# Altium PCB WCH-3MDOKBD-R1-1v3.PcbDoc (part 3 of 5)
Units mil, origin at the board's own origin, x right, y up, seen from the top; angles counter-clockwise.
Board outline 11710.74 x 4477.49 mil, 2 copper layers (Top Layer, Bottom Layer); 422 components, 246 nets, 927 pads, 1295 vias.
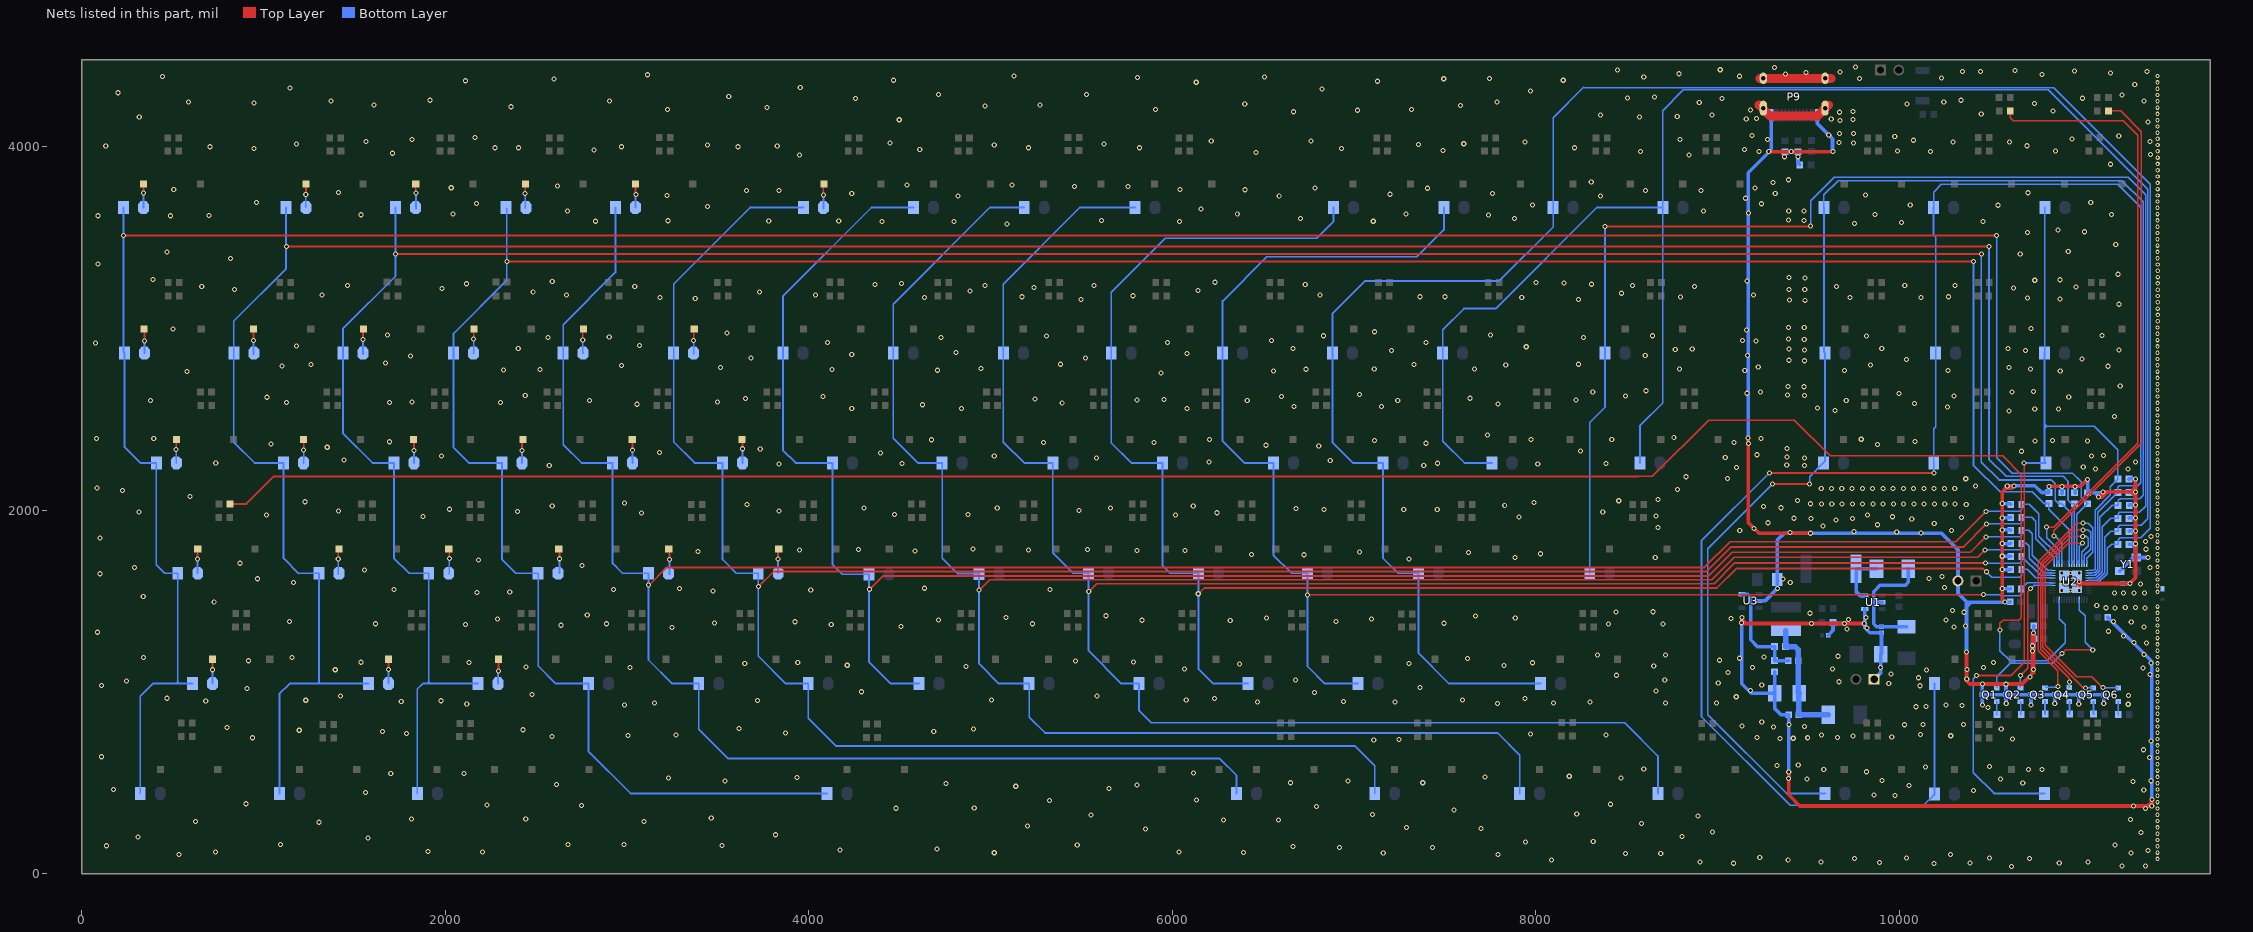
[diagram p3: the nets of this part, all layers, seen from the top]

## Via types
v1: diameter 28, hole 16, Top Layer to Bottom Layer, tented both sides, 1167 vias
v2: diameter 24, hole 12, Top Layer to Bottom Layer, tented both sides, 128 vias

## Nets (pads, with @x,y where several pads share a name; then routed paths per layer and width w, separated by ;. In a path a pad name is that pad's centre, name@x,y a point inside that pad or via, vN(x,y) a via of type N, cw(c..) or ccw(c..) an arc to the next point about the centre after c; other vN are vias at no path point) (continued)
BT-: C2.1 C3.1 C5.1 C6.1 C7.1 C8.1 C9.1 C11.2 C12.2 C13.2 C14.1 E1.0 J1.1 P7.2 P9.0 P9.A1 P9.B1 Q1.3 Q2.3 Q3.3 Q4.3 Q5.3 Q6.3 R10.2@9370.04,3970.81 R11.2@9442.13,3971.71 R128.1 R129.1 R133.1 RJ1.1 RJ2.1 RJ3.1 RJ4.1 RJ5.1 RJ6.1 RJ7.1 RJ8.1 RJ9.1 RJ10.1 RJ11.1 RJ12.1 RJ13.1 RJ14.1 RJ15.1 RJ16.1 RJ17.1 U1.4 U2.0 U3.2 Y1.2 Y1.4 | length 18642.1
  Top Layer w20: v1(9134.61,1409.74) 9134.61,1395.68 ; v1@9168.65,2396.61 v1(9168.65,2366) 9168.65,1931.1 9227.54,1872.21 v1(9511.69,1872.21) ; v1(9281,3971.58) v1(9404.61,3971.58) v1@9636.45,3971.58 ; v1@9390.47,558.96 v1(9390.47,523.09) 9390.47,433.13 9452.07,371.53 11365.06,371.53 ; v1(9806.35,1376.09) v1(9697.77,1376.09) 9154.21,1376.09 ; v1(10368.6,1218.87) 10368.6,1061.6 10387.56,1042.64 10674.23,1042.64 10731.29,1099.71 ; v1(10579.88,1493.79) 10565.71,1507.95 v1(10565.71,1567.63) v1(10565.71,1671.91) v1(10565.71,1745.7) v1(10565.71,1814.83) v1(10565.71,1890.97) v1(10565.71,1956.97) v1(10565.71,2035.15) 10565.71,2100.44 v1@10586.22,2120.95 ; v1(10593.28,2131.64) v1@10628.4,2131.64 ; v1@10595.1,2129.83 v1@10586.22,2120.95 ; v1(10629.12,2132.36) v1@10628.4,2131.64 ; v1(10731.29,1253.25) v1@10731.29,1224.34 ; v1(10732.16,1224.34) v1@10732.16,1225.2 ; v1(10822.87,2129.88) 10994.92,2129.88 v1(11034.05,2169.01) ; 10978.98,1596.12 11003.83,1596.12 ; v2@10988.26,1611.7 11003.83,1596.12 ; 10991.91,1584.2 11003.83,1596.12 ; v1@11120.34,2100.12 v1@11125.31,2100.12 ; v1(11298.76,2171.58) 11298.76,2124.66 ; v1(11389.33,408.45) v1@11389.33,395.8 ; 9134.61,1395.68 9154.21,1376.09 ; 9134.61,1395.68 9134.61,1379.16 9131.54,1376.09 9154.21,1376.09 ; v1@10586.22,2120.95 10617.7,2120.95 v1@10628.4,2131.64 ; 10731.29,1099.71 v1@10731.29,1224.34 ; 10731.29,1099.71 10738.13,1106.55 v1@10738.13,1231.18 ; v1@10731.29,1224.34 v1@10732.16,1225.2 ; v1@10732.16,1225.2 10732.16,1317.23 v1(10738.13,1323.21) v1@10738.13,1231.18 ; v1@10732.16,1225.2 v1@10738.13,1231.18 ; 11003.83,1596.12 v1(11267.28,1596.12) 11298.76,1627.61 v1(11298.76,1814.3) v1(11298.76,1885.75) v1(11298.76,1957.21) v1(11298.76,2028.66) 11298.76,2075.34 ; v1@11125.31,2100.12 v1(11095.82,2070.63) 11116.06,2070.63 11145.55,2100.12 ; v1@11125.31,2100.12 11145.55,2100.12 ; 11145.55,2100.12 11273.98,2100.12 ; 11273.98,2100.12 11298.76,2075.34 ; 11273.98,2100.12 11274.22,2100.12 ; 11274.22,2100.12 11298.76,2124.66 ; 11274.22,2100.12 v1(11298.76,2100.12) ; 11298.76,2075.34 v1(11298.76,2100.12) ; v1(11298.76,2100.12) 11298.76,2124.66 ; 11365.06,371.53 v1(11387.76,371.53) 11389.33,373.1 v1@11389.33,395.8 ; 11365.06,371.53 v1@11389.33,395.8
  Top Layer w50: 9228.25,4229.01 9289.92,4167.33 9547.79,4167.33 P9.0@9608.53,4228.08 ; P9.0@9233.05,4374.91 P9.0@9251.14,4374.91 P9.0@9591.3,4374.91 9622.76,4374.91
  Bottom Layer w20: v1(9131.93,1379.85) 9131.93,1407.06 v1(9134.61,1409.74) ; v1@9131.93,1380.56 9131.93,1045.07 9185.17,991.82 C12.2@9313.23,991.82 ; v1@9168.14,2363.04 9168.14,3855.24 9294.26,3981.36 P9.A1@9294.26,4172.15 ; U3.2@9228.25,1500.05 9260.48,1500.05 v1(9328.59,1568.15) C13.2@9328.59,1617.07 ; C12.2@9310.83,989.42 C12.2@9313.23,991.82 ; R133.1@9313.87,1111.26 9313.87,992.47 C12.2@9313.23,991.82 ; C13.2@9331.11,1614.55 C13.2@9328.59,1617.07 ; v1(9368.29,3943.47) 9370.04,3945.23 R10.2@9370.04,3970.81 9370.94,3971.71 R11.2@9442.13,3971.71 v1@9442.13,3943.81 ; v1@9390.37,523.09 v1@9390.42,523.14 ; v1(9390.47,523.09) v1@9390.42,523.14 ; v1(9391.29,558.96) 9391.29,524.01 v1@9390.42,523.14 ; v1(9442.47,3943.47) v1@9442.13,3943.81 ; R128.1@9452.55,3898.85 9442.13,3909.27 v1@9442.13,3943.81 ; P9.B1@9548.19,4172.15 9548.19,4125.84 9631.52,4042.51 v1@9631.52,3971.58 ; C5.1@9607.68,1311.74 9634.85,1338.91 R129.1@9634.85,1380.06 9635.78,1381 9640.69,1376.09 v1(9697.77,1376.09) ; U1.4@9809.52,1455.37 9809.52,1352.67 9837.07,1325.11 C3.1@9901.41,1325.11 9901.41,1209.4 C2.1@9898.17,1206.15 9898.17,1106.53 J1.1@9860.69,1069.05 ; v1(10368.6,1218.87) 10368.6,1469.66 ; v1(10456.21,928.26) Q1.3@10456.21,984.15 ; v1@10456.21,1044.2 Q1.3@10456.21,984.15 ; v1(10565.71,1567.63) 10567.31,1566.03 RJ11.1@10610.94,1566.03 ; v1(10565.71,1671.91) 10610.27,1671.91 RJ10.1@10611.9,1673.55 ; v1(10565.71,1745.7) 10611.31,1745.7 RJ9.1@10611.9,1745.11 ; v1(10565.71,1814.83) 10610.08,1814.83 RJ8.1@10611.9,1816.66 ; v1(10565.71,1890.97) 10609.15,1890.97 RJ7.1@10611.9,1888.22 ; v1(10565.71,1956.97) 10609.11,1956.97 RJ6.1@10611.9,1959.77 ; v1(10565.71,2035.15) 10608.07,2035.15 RJ5.1@10611.9,2031.32 ; v1@10586.15,1042.93 10585.92,1042.7 Q2.3@10585.92,984.15 ; v1(10587.65,935.73) 10585.92,937.46 Q2.3@10585.92,984.15 ; v1(10593.28,2131.64) 10595.95,2134.31 10744.21,2134.31 10782.35,2096.17 RJ4.1@10822.08,2096.17 v1@10822.08,2129.88 ; C6.1@10610.12,1495.6 10606.4,1491.87 10390.81,1491.87 ; v1(10723.81,926.49) 10723.81,982.13 Q3.3@10721.79,984.15 ; C9.1@10739.29,1363.92 10739.29,1294.13 C8.1@10741.11,1292.32 C8.1@10741.11,1281.6 ; v1(10854.28,936.5) 10855.32,937.54 Q4.3@10855.32,984.15 ; Q4.3@10855.32,985.04 Q4.3@10855.32,984.15 ; RJ3.1@10894.47,2090.85 v1@10894.47,2129.89 ; RJ2.1@10966.38,2094.01 v1(10966.38,2128.9) ; v1(10986.51,933.46) 10987.29,934.24 Q5.3@10987.29,984.06 ; v1@11034.95,2172.09 RJ1.1@11034.95,2095.15 11075.48,2095.15 ; v1(11123.7,934.83) Q6.3@11123.7,983.69 11123.25,984.15 Q4.3@10855.32,984.15 ; C14.1@11145.05,1410.61 11387.76,1167.9 v1(11387.76,371.53) ; Y1.4@11211.35,1663.76 11286.16,1738.56 Y1.2@11301.9,1738.56 ; C7.1@11228.28,1596.06 11267.21,1596.06 v1(11267.28,1596.12) ; RJ16.1@11262.57,2097.64 11265.05,2100.12 v1(11298.76,2100.12) ; RJ17.1@11262.9,2169.74 11264.73,2171.58 v1(11298.76,2171.58) ; RJ12.1@11263.19,1811.41 RJ12.1@11278.15,1811.41 ; RJ13.1@11263.19,1882.98 11265.96,1885.75 v1(11298.76,1885.75) ; RJ14.1@11263.19,1954.56 11265.84,1957.21 v1(11298.76,1957.21) ; RJ15.1@11263.22,2026.18 11265.7,2028.66 v1(11298.76,2028.66) ; v1(11366.65,1738.56) Y1.2@11301.9,1738.56 ; C12.2@9313.23,991.82 9313.23,909.25 9347.79,874.69 C11.2@9390.37,874.69 9390.37,523.19 v1@9390.42,523.14 ; C13.2@9328.59,1617.07 C13.2@9328.59,1618.92 ; C13.2@9328.59,1617.07 C13.2@9327.66,1618 C13.2@9328.59,1618.92 ; C13.2@9328.59,1618.92 9328.59,1834.58 9367.15,1873.15 10229.88,1873.15 10321.86,1781.17 P7.2@10321.86,1610.46 10321.86,1542.72 10372.71,1491.87 ; 10368.6,1469.66 10368.6,1487.76 10372.71,1491.87 ; 10368.6,1469.66 10390.81,1491.87 ; 10372.71,1491.87 10390.81,1491.87 ; Q1.3@10456.21,984.15 Q2.3@10585.92,984.15 ; Q2.3@10585.92,984.15 Q3.3@10721.79,984.15 ; Q3.3@10721.79,984.15 Q4.3@10855.32,984.15 ; v1@10732.16,1254.11 v1(10732.16,1224.34) 10741.11,1233.29 v1@10741.11,1263.06 ; v1@10732.16,1254.11 v1@10741.11,1263.06 ; v1@10732.16,1254.11 v1(10731.29,1253.25) 10731.29,1271.79 C8.1@10741.11,1281.6 ; v1@10741.11,1263.06 C8.1@10741.11,1281.6 ; 11075.48,2095.15 11096.31,2095.15 ; 11075.48,2095.15 11095.82,2074.81 v1(11095.82,2070.63) v1@11101.3,2076.11 ; 11096.31,2095.15 11120.34,2095.15 v1@11101.3,2076.11 ; 11096.31,2095.15 11101.3,2090.17 v1@11101.3,2076.11 ; RJ12.1@11278.15,1811.41 11298.76,1790.79 ; RJ12.1@11278.15,1811.41 11295.87,1811.41 v1(11298.76,1814.3) 11298.76,1790.79 ; 11298.76,1790.79 11298.76,1741.7 Y1.2@11301.9,1738.56
  other v1: 10616.69,38.55 11353.1,41.42 11224.51,42.39 10190.38,55.82 9086.16,56.93 10879.06,57.29 10387.53,58.23 9889.91,61.17 8903.75,63.22 11036.8,63.54 9568.59,64.45 8086.02,75.8 9388.09,75.8 9752.21,82.28 10715.08,83.84 10039.73,85.55 10494.88,86.96 9231.81,87.96 535.01,104.42 10280.92,104.14 7792.09,105.61 8493.74,110.26 8686.74,110.4 11273.82,112.97 5020.42,114.86 7160.4,114.45 6390.92,115.13 737.76,118.41 2205.95,118.41 6037.59,118.17 1905.1,121.77 11366.64,126.51 4172.96,130.96 4706.54,136.45 6920.63,142.54 7430.58,143.5 6665.04,148.63 136.5,153.36 3522.04,155.25 11185.84,156.49 5477.15,157.77 1094.31,160.35 2676.82,160.11 2982.85,160.11 7943.19,174.35 8315.79,176.73 1576.73,195.31 311.28,202.3 8803.5,203.91 3818.36,213.54 11328.94,227.07 8972.36,229.76 5852.5,246.23 7698.76,247.92 7288.88,252.82 5203.02,261.33 8582.03,275.46 1305.86,282.43 625.89,286.2 3094.58,286.4 6583.62,294.38 6280.78,295.65 11270.93,298.62 1814.44,300.18 2443.66,300.98 3463.75,305.83 8892.29,316.81 5553.89,321.88 7100.41,324.88 8224.94,328.47 7549.25,349.97 11353.41,358.72 4479.13,359.48 4910.61,361.84 6792.86,368.44 11287.35,371.04 2749.69,373.84 2230.78,377.97 8410.47,381.74 905.55,384.08 5324.85,401.44 6132.53,404.36 9974.66,430.5 9860.11,432.9 1562.74,447 10406.53,456.16 11343.91,460.69 176.56,462.83 5650.76,468.45 5139.06,480.63 10053.68,485.21 5806.38,486.73 2613.67,490.42 4755.88,495.28 6649.77,499.9 7377.84,499.9 10678.41,499.53 11284.94,505.6 3539.61,509.19 6966.03,509.79 11384.5,511.03 9904,512.56 10555.61,520 9491.58,520.73 3227.75,526.05 8468.31,526.26 3934.94,529.28 7719.46,530.66 8183.47,535.31 1701.01,551.66 2104.85,551.66 6116.06,552.62 9817.67,560.21 10710.81,572.02 9583.81,572.61 10785,572.87 8593.5,575.68 10142.28,586.6 10495.07,588.22 9327.39,595.55 9443.11,597.36 11376.05,637.75 108.53,642.76 11342.86,681.19 11383.89,730.07 7108.3,734.59 7247.74,737.43 10621.83,741.08 9341.84,743.45 9416.01,744.43 940.04,747.56 9495.36,747.57 9659.7,747.81 9216.59,748.17 9957.65,752.26 2586.9,755.26 9745.25,756.94 10282.48,758.5 3007,760.38 3269.89,762.05 9571.29,762.05 8385.11,763.06 10115.38,764.75 7970.76,768.61 1787.68,770.63 3873.21,773.34 1654.47,780.88 4687.87,781.88 1197.35,788.68 2428.07,791.12 10560.11,795.79 4906.46,796.45 3616.28,797.32 800.29,804.2 9308.3,805.82 9477.15,809.68 9133.78,811.58 10028.23,818.69 9392.99,819.55 10128.51,819.55 10352.76,820.97 9242.79,834.64 10486.92,912.87 10090.56,917.97 10146.49,918.79 10344.71,924.55 2987.53,926.41 10255.06,927.84 11258.52,931.62 2118.99,932.41 7788.82,934.78 8097.61,938.57 3151.89,939.06 8713.59,939.19 8994.3,939.06 7225.45,942.87 6468.27,944.71 8296.84,944.66 1758.39,947.2 6942.44,947.67 682.93,949.14 1976.89,950.96 3717.4,951.86 1233.08,953.42 5005.03,955.79 6076.55,955.28 7596.33,955.28 470.61,964.58 6232.11,964.26 7940.38,964.26 9102.54,972.65 1424.01,976.98 5586.8,977.11 11260.53,980.01 2477.6,985.41 6782.59,997.17 4289.55,1000.47 8660.96,1005.55 9179.89,1008.38 909.85,1019.13 7362.98,1024.09 10113.08,1033.27 108.53,1034.28 9242.36,1038.05 10586.19,1041.62 10456.15,1042.69 9941.08,1046.14 9003.34,1049.26 9668.23,1055.32 248.01,1059.79 6677.88,1065.98 8709.01,1065.04 10370.12,1069.9 10105.07,1077.29 10717.71,1082.27 8442.72,1091.37 11378.35,1096 9953.76,1098.55 9056.37,1107.21 10149.09,1119.3 1395.37,1121.39 10370.6,1121.91 10737.76,1122.39 6067.57,1125.81 9631.8,1125.29 11339.29,1131.18 3017.03,1132.92 10463.35,1133.21 9192.39,1134.88 9896.29,1134.05 2443.88,1137.13 4864.93,1138.54 8648.53,1142.74 7823.7,1143.76 4211.82,1146.2 6369.73,1152.74 3648.34,1155.91 7303.15,1155.73 11382.83,1158.72 7982.35,1160.01 3939.8,1160.77 10518.17,1161.69 1537.8,1162.42 2131.55,1162.08 5785.74,1164.76 5468.01,1169 918.28,1170.85 9009.94,1173.57 7623.26,1182.65 9120.55,1184.85 1157.32,1188.52 340.66,1189.76 9254.86,1191.1 9662.72,1195.67 8339.23,1202 8713.59,1201.57 11345.51,1205.81 11358.65,1268.24 11289.54,1271.56 11232.74,1305.99 87.56,1327.92 11150.37,1333.18 9711.82,1346.48 9821.78,1350.39 3246.97,1353.28 10299.66,1356.64 11345.3,1357.36 4508.1,1359.8 10363.7,1361.33 2636.84,1366.08 2112.04,1370.35 4123.86,1370.05 8398.82,1372.89 8698.34,1373.95 1617.1,1374.62 2888.57,1374.62 5231.92,1374.51 9515.86,1376.4 7494.61,1377.11 3481.64,1378.88 11275.04,1383.8 3924.05,1385.42 6900.45,1385.93 1143.49,1387.42 11178.33,1387.58 6318.88,1392.07 5834.26,1393.94 4713.03,1395.66 10256.76,1395.3 9720.27,1398.81 2286.97,1400.22 7096.72,1401.05 9073.62,1402.75 6519.32,1407.03 7886.53,1407.03 5086.19,1408.51 9815.53,1408.18 7668.13,1416.01 5635.1,1418.22 2781.9,1421.55 9507.36,1432.14 10355.89,1437.85 8441.8,1438.79 8644.94,1440.3 10292.8,1447.56 11186.79,1461.24 11349.89,1461.71 11135.56,1462.65 11242.26,1463.59 11298.19,1464.06 11085.27,1475.81 729.62,1494.08 339.25,1523.68 11182.77,1543.07 11232,1543.07 11289.42,1543.07 11348,1543.96 2176.04,1545.28 2355.24,1549.55 3473.11,1553.82 4011.15,1559.6 1719.5,1562.35 2926.97,1562.35 5328.27,1562.7 3290.08,1568.41 4636.18,1569.85 10247.97,1574.19 11326.87,1593.48 1164.83,1600.75 9399.25,1600.5 9359.88,1620.18 968.56,1622.08 10162.22,1623.47 10233.97,1633.82 101.54,1649.52 1557.36,1669.02 290.3,1684.48 11378.35,1684.48 2752.04,1694.62 870.43,1707.42 2184.57,1724.48 7302.6,1731.42 7884.77,1738.16 8656.76,1739.72 6724.94,1753.89 6434.99,1756.14 8025.28,1759.74 7628.53,1767.38 7030.63,1769.63 3392.04,1771.42 4584.39,1774.51 5805.14,1777.49 6070.13,1777.49 3950.19,1780.47 5209.65,1780.47 4274.73,1783.44 5534.19,1783.44 11355.46,1784.47 4902.97,1786.42 11353.07,1826.66 101.54,1845.28 11382.83,1854.93 10119.52,1874.37 9397.3,1875.76 9984.97,1879.87 9750.63,1882.93 9121.76,1887.12 10285.76,1888.31 9199.25,1898.38 8672.24,1904.23 9580.16,1911.41 9879.55,1918.86 10191.4,1925.87 9276.63,1929.82 9650.4,1945.16 10067.66,1950.07 9512.5,1952.98 9742.49,1952.36 9419.7,1954.91 10342.33,1959.59 7906.12,1962.3 9962.15,1962.98 1877.35,1963.42 8660.35,1967.11 1018.21,1971.9 6018.59,1973.73 9824.31,1973.57 4472.24,1974.58 4876.97,1974.58 3080.56,1984.75 6244.87,1984.83 315.82,1988.98 8367.88,1989.44 2397.68,1991.03 1414.4,1993.66 3836.96,1995.08 5486.15,1997.22 6835.08,2003.39 7273.39,2003.39 7457.71,2003.39 2024.84,2004.21 6679.98,2007.88 4305.16,2010.11 5660.82,2010.45 5037.01,2012.02 9348.05,2012.66 9252.55,2019.13 2589.39,2022.22 6115.2,2023.05 7828.58,2025.87 10367.37,2029.38 3660.44,2030.19 9571.29,2032.46 9627.77,2032.46 9684.25,2032.46 9740.74,2032.46 9797.22,2032.46 9853.7,2032.46 9910.18,2032.46 9966.67,2032.46 10023.15,2032.46 10079.63,2032.46 10136.12,2032.46 10192.6,2032.46 10249.08,2032.46 10305.56,2032.46 9511.18,2034.42 2987.08,2038.11 7988.71,2042.04 1229.71,2045.33 8455.72,2051.28 9439.91,2053.17 8671.4,2058.04 597.36,2074.35 11120.14,2099.7 226.15,2108.49 8780.04,2112.28 9569.74,2118.47 9626.22,2118.47 9682.71,2118.47 9739.19,2118.47 9795.67,2118.47 9852.16,2118.47 9908.64,2118.47 9965.13,2118.47 10021.61,2118.47 10078.09,2118.47 10134.58,2118.47 10191.06,2118.47 10247.54,2118.47 10304.03,2118.47 85.35,2121.29 10893.83,2129.62 10419.28,2131.58 9055.05,2172.46 10364.97,2172.31 8826.48,2183.08 11256.74,2224.76 11079.57,2226.43 9104.79,2234.04 11011.16,2236.97 2572.82,2245.02 7383.06,2244.65 9477.15,2244.65 9380.01,2248.1 8010.54,2253.72 3835.66,2254.16 8386.35,2255.92 4513,2256.9 738.16,2257.82 7459.95,2257.38 6201.6,2264.06 11298.19,2264.06 6868.71,2273.48 1444.59,2275.42 9477.38,2285.35 5583.97,2287.1 9042.02,2288.52 9381.19,2291.74 1979.75,2296.22 5020.42,2297.35 11055.47,2298.33 11123.09,2298.97 9217.3,2303.91 4395.39,2312.72 3178.7,2317.55 10671.72,2323.46 8244.57,2324.42 3733.37,2334.62 9382.23,2339.05 1351.26,2345.42 6805.86,2351.78 6515.9,2356.28 9878.63,2359.54 1041.17,2362.51 7394.77,2367.52 5290.86,2371.35 5898.78,2371.86 9089.12,2372.34 1694.56,2375.42 10086,2377.03 10745.79,2379.4 11034.6,2380.22 10842.12,2383.01 7111.57,2383.44 4676.46,2386.42 7972.44,2387.75 8417.32,2387.76 6205.65,2388.96 9789.86,2389.52 81.09,2394.35 397.27,2394.17 9238.27,2394.35 9166.98,2396.61 8758.74,2398.69 7733.48,2412.24 11182.58,2513.7 10602.24,2544.17 9644.68,2547.81 10744.42,2554.94 10874.4,2556.02 4236.57,2558.63 4841.1,2558.63 6080.93,2558.63 9549.07,2561.53 10264.52,2567.04 6668.75,2569.81 7149.76,2569.81 4625.93,2579.12 3054.97,2582.09 7792.07,2584.25 10082.67,2585.47 5394.42,2589.37 1126.43,2590.62 1693.9,2590.62 2304.04,2590.62 1817.63,2594.89 3498.83,2594.49 9707.45,2602.06 379.76,2603.42 2794.7,2603.42 6412.51,2603.53 7240.44,2603.08 5806.38,2605.78 8219.69,2605.78 5955.36,2607.47 5245.84,2609.86 3652.96,2613.97 7638.38,2614.99 1019.76,2620.49 10931.59,2621.06 6601.32,2623.76 4077.74,2625.23 2440.57,2629.02 8493.91,2628.26 10300.86,2628.37 9477,2630.17 9384.52,2632.08 7030.63,2635 9997.02,2639.98 9162.32,2642.25 10618.45,2648.27 9235.98,2649.47 8312.72,2650.18 10736.68,2652.17 8604.99,2656.26 9387.07,2678.48 9475.09,2678.16 11214.58,2682.91 5937.48,2753.31 580.29,2761.29 10884.8,2763.9 6556.36,2765.36 9149,2767.76 9696.97,2767.2 4707.9,2768.68 10266.97,2768.08 2321.1,2769.82 4128.98,2773.8 2521.64,2774.09 6736.18,2774.35 7110.86,2775.71 7662.71,2775.16 8790.61,2776.61 10720.55,2776.21 4948.69,2778.93 10603.68,2783.56 3514.19,2784.05 9223.22,2787.11 11146.31,2790.81 1102.1,2791.99 2969.64,2795.42 7834.46,2798.39 9840.67,2798.82 1262.96,2799.69 5385.07,2801.69 7329.58,2801.33 8235.32,2802.13 1672.57,2808.22 9478.3,2821.15 9393.37,2824 10037.9,2828.81 11004.12,2829.98 3683.26,2835.28 5522.49,2835.28 1809.1,2846.62 8601.8,2850.78 9164.8,2850.61 4236.57,2855.78 6080.93,2860.9 4810.36,2866.02 7205.95,2878.33 10692.43,2878.16 11207.24,2879.31 9478.3,2880.39 8766.78,2882.44 9393.37,2885.39 8860.29,2886.74 6664.28,2887.88 9902.82,2887.88 2402.17,2889.29 10596.43,2889.47 7947.27,2898.23 1181.89,2902.09 3068.93,2904.27 76.82,2919.16 7394.76,2920.46 4103.36,2922.38 5973.33,2922.38 9211.38,2930.41 6545.12,2931.7 9137.62,2932.19 9476.16,2938.92 9390.47,2941.01 2566.4,2947.99 4728.39,2947.99 8262.4,2949.68 2902.93,2951.59 9818.42,2956.81 5307.32,2958.24 6832.84,2958.67 8642.26,2958.67 11114.38,2959.11 1682.73,2962.97 7749.88,2963.57 3550.06,2973.61 7112.52,2980.87 9159.3,2989.83 502.72,2996.14 10722.65,2998.28 9389.8,3003.15 9476.59,3003.96 11207.24,3131.76 9481.32,3153.74 9394.44,3155.02 5496.88,3158.05 8235.42,3158.72 10883.7,3160.78 3375.87,3163.17 10705.25,3166.58 3181.19,3168.29 4636.18,3168.29 7922.59,3169.24 9727.95,3169.79 10119.41,3169.79 8794.83,3172.77 5174.12,3173.42 7361.72,3173.42 7500.05,3173.42 10269.06,3173.49 5783.78,3178.54 1322.69,3183.69 2668.54,3183.33 4036.76,3183.66 6813.54,3183.66 9197.87,3183.69 8471.43,3192.43 3729.37,3199.03 2484.42,3199.15 4887.22,3204.15 6140.45,3208.19 9479.18,3212.27 840.55,3213.56 9392.3,3213.55 1981.69,3218.71 10628.35,3220.26 5238.32,3224.82 10970.75,3227.52 3042.86,3229.77 9654.16,3229.22 661.35,3230.62 8871.52,3230.64 1463.49,3234.89 4969.19,3234.89 5568.61,3234.89 10305.4,3234.82 8532.12,3235.14 10029.23,3235.37 4364.64,3240.02 6731.57,3240.02 8305.1,3241.88 2117.62,3244.6 4511.05,3245.62 8154.53,3248.6 8001.69,3250.98 6236.01,3253.24 2589.42,3258.13 9160.93,3259.66 10744.42,3263.79 10883.7,3266.69 392.55,3269.02 9479.61,3277.32 9392.72,3278.59 11202.9,3297.16 89.61,3354.36 819.22,3384.22 10664.63,3408.88 469.35,3418.36 10928.68,3421.94 11189.84,3459.66 10705.25,3526.4 11017.19,3530.75 10872.1,3539.46 5091.79,3573.13 9753.85,3575.76 10010.57,3582.3 10458.95,3586.47 4403.62,3587.22 4798.47,3587.22 6039.51,3587.95 2827.68,3588.39 7105.57,3588.39 3780.32,3590.04 4165.44,3590.73 3225.74,3591.22 5610.73,3592.87 9473.9,3593.42 9389.58,3596.47 6705.96,3603.76 7883.57,3603.78 89.61,3618.89 489.2,3618.8 701.55,3619.13 7740.5,3623.59 1536.64,3624.26 9865.04,3626.45 11166.62,3626.51 7284.96,3628.45 2043.83,3629.38 6357.58,3629.38 9170.68,3633.53 2673.99,3644.75 8922.61,3644.1 9391.29,3644.75 9474.28,3644.16 6157.77,3655 3442.47,3670.36 10542.35,3676.46 7981.25,3677.88 10059.63,3677.14 9240.5,3684.86 2171.91,3685.73 962.84,3690.86 11052.36,3691.23 9154.12,3714.85 4820.61,3726.72 6588.12,3726.72 8355.63,3726.72 3220.8,3729.46 9814.35,3732.73 7197.78,3736.97 9316.89,3740.75 4236.57,3742.09 7761.33,3742.09 10706.7,3745.47 1413.68,3747.21 3657.64,3757.46 3836.96,3757.46 8604.17,3758.5 8908.7,3758.5 506.87,3762.58 6400.43,3762.09 6042.36,3763.4 7403.34,3770.2 9206.33,3770.83 2033.58,3772.83 6784.21,3772.23 5461.26,3779.01 5757.4,3779.01 2617.63,3783.07 5117.17,3787.47 4541.45,3788.11 9304.62,3801.03 8304.59,3804.28 9389.59,3817.08 11161.63,3902.08 3949.67,3952.14 8841.92,3952.9 11381.03,3955.98 1710.83,3962.39 6460.04,3967.51 8575.93,3972.64 9634.7,3972.2 9226.94,3973.1 10169.88,3973.26 10857.89,3974 9989.13,3974.85 7489.81,3977.76 2819.2,3980.34 4610.56,3982.88 9146.92,3983.58 947.47,3988 6931.38,3988.01 2273.61,3992.85 2402.45,3993.13 5209.97,3993.13 5819.64,3993.13 8212.18,3993.13 706.68,3998.25 2971.13,3998.25 3611.54,3998.25 132.88,4003.37 3826.71,4003.37 10702.34,4003.73 3442.47,4008.5 5020.41,4008.5 7354.67,4010.18 1183.13,4013.62 5624.83,4013.1 7603.1,4015.05 4446.61,4018.74 9748.34,4018.67 9668.07,4020.94 7940.65,4023.87 10294.65,4024.04 10606.45,4024.67 1563.99,4027.34 11377.48,4027.47 6762.31,4028.99 6214.29,4030.02 10077.03,4034.19 8793.49,4038.02 9273.94,4037.55 1818.41,4039.23 10949.06,4041.72 2164.47,4049.14 9974.13,4055.8 11206.6,4057.58 9188.87,4060.84 9610.93,4063.05 9748.34,4070.92 9670.34,4072.05 11366.49,4134.23 9672.39,4143.36 4497.85,4146.82 9743.86,4148.26 9624.64,4150.4 9157.31,4151.53 9214.43,4153.55 317.31,4162.19 8570.8,4162.19 8777.87,4164.42 8355.63,4172.44 8969.57,4172.45 10449.91,4179.62 9671.09,4188.29 6667.14,4191.01 9744.92,4192.08 10843.95,4195.31 7019.14,4199.2 9180.09,4201.33 3222.17,4203.18 5906.74,4203.18 7315.62,4203.18 3770.35,4213.42 2361.47,4218.55 4969.18,4223.67 7586.05,4224.51 1608.36,4228.79 5271.45,4228.79 6398.56,4233.92 10042.48,4233.7 10742.82,4235.42 947.47,4239.04 8898.61,4242.36 588.84,4244.16 7786.95,4244.17 10243.91,4245.21 1372.69,4249.29 2904.53,4249.29 11346.26,4251.12 10338.9,4253.95 1915.75,4254.41 4257.06,4264.66 9024.88,4264.28 8503.07,4265.46 11006.09,4265.06 8651.73,4272.29 3560.3,4274.9 11224.89,4282.58 4713.02,4285.15 5527.61,4285.15 199.48,4295.39 7971.39,4305.64 6823.79,4315.89 1147.27,4321.01 3953.48,4324.88 11294.56,4341.02 6131.81,4353.28 7129.65,4358.83 2111.6,4361.44 4467.09,4364.23 8150.61,4364.44 2599.39,4370.55 7493.36,4372.66 9779.43,4372.95 7745.57,4374.83 10232.4,4376.22 5807.6,4379.3 6507.52,4382.57 8593.62,4383 446.09,4385.95 9120.88,4386.36 5128.77,4387.18 3112.28,4394.62 10784.44,4395.71 9374.31,4399.42 8786.27,4400.19 11161.21,4404.32 9486.06,4406.76 9673.87,4410.31 10347.4,4412.73 10446.27,4413.44 11362.1,4413.15 10962.99,4415.14 10634.68,4417.56 8449.96,4419.97 9014.44,4421.84 9313.27,4433.47 9758.82,4436.05
  other v2: 11419.5,80.86 11419.5,115.56 11419.5,150.26 11419.5,184.96 11419.5,219.66 11419.5,254.36 11419.5,289.07 11419.5,323.77 11419.5,358.47 11419.5,393.17 11419.5,427.87 11419.5,462.57 11419.5,497.28 11419.5,531.98 11419.5,566.68 11419.5,601.38 11419.5,636.08 11419.5,670.78 11419.5,705.49 11419.5,740.19 11419.5,774.89 11419.5,809.59 11419.5,844.29 11419.5,878.99 11419.5,913.7 11419.5,948.4 11419.5,983.1 11419.5,1017.8 11419.5,1052.5 11419.5,1087.2 11419.5,1121.91 11419.5,1156.61 11419.5,1191.31 11419.5,1226.01 11419.5,1260.71 11419.5,1295.42 11419.5,1330.12 11419.5,1364.82 11419.5,1399.52 11419.5,1434.22 11419.5,1468.92 11419.5,1549.49 10940.73,1557.7 11419.5,1583.53 10892.73,1605.7 10988.73,1605.7 11419.5,1618 11419.5,1652.7 10940.73,1653.7 11419.5,1687.4 11419.5,1722.1 11419.5,1756.8 11419.5,1791.51 11419.5,1826.21 11419.5,1860.91 11419.5,1895.61 11419.5,1930.31 11419.5,1965.01 11419.5,1999.72 11419.5,2034.42 11419.5,2069.12 11419.5,2103.82 11419.5,2138.52 11419.5,2173.22 11419.5,2207.93 11419.5,2242.63 11419.5,2277.33 11419.5,2312.03 11419.5,2346.73 11419.5,2381.43 11419.5,2416.14 11419.5,2450.84 11419.5,2485.54 11419.5,2520.24 11419.5,2554.94 11419.5,2589.65 11419.5,2624.35 11419.5,2659.05 11419.5,2691.99 11419.5,2726.7 11419.5,2761.4 11419.5,2796.1 11419.5,2830.8 11419.5,2865.5 11419.5,2900.2 11419.5,2934.91 11419.5,2969.61 11419.5,3004.31 11420.84,3038.56 11420.84,3073.27 11420.84,3107.97 11420.84,3142.67 11420.84,3177.37 11420.84,3212.07 11420.84,3246.77 11420.84,3281.48 11420.84,3316.18 11420.84,3350.88 11419.52,3385.13 11419.52,3419.84 11419.52,3454.54 11419.52,3489.24 11419.52,3523.94 11419.52,3558.64 11419.52,3593.35 11419.52,3628.05 11419.52,3662.75 11419.52,3697.45 11420.17,3730.4 11420.17,3765.1 11420.17,3799.81 11420.17,3834.51 11420.17,3869.21 11420.17,3903.91 11420.17,3938.61 11420.17,3973.31 11420.17,4008.02 11420.17,4042.72 11419.52,4075 11419.52,4109.71 11419.52,4144.41 11419.52,4179.11 11419.52,4213.81 11419.52,4248.51 11419.52,4283.21 11419.52,4317.92 11419.52,4352.62 11419.52,4387.32
CL0: D1.2 D7.2 D13.2 D19.2 D28.2 D34.2 RJ1.2 U2.20 | length 16248
  Top Layer w10: v1(231.49,3510.98) v1(10534.99,3510.98)
  Bottom Layer w7: U2.20@10975.43,1704.68 10975.43,1975.57 RJ1.2@11034.38,2034.52
  Bottom Layer w10: D1.2@230.22,3664.02 230.22,2869.68 D7.2@236.44,2863.47 236.44,2346.22 323.49,2259.16 D13.2@411.11,2259.16 411.11,1699.56 458.76,1651.91 D19.2@528.99,1651.91 528.99,1054.33 ; D34.2@322.75,440.87 322.75,976.26 391.71,1045.22 519.88,1045.22 ; D28.2@610.9,1045.22 538.09,1045.22 ; v1@10535.73,3510.98 10535.73,2288.04 10620.96,2202.81 10951.86,2202.81 10999.82,2154.86 10999.82,2069.66 RJ1.2@11034.95,2034.52 ; 519.88,1045.22 528.22,1045.22 ; 519.88,1045.22 528.99,1054.33 ; 528.22,1045.22 538.09,1045.22 ; 528.22,1045.22 528.99,1045.99 528.99,1054.33 ; 528.99,1054.33 538.09,1045.22
CL1: D2.2 D8.2 D14.2 D20.2 D29.2 D35.2 RJ2.2 U2.19 | length 15685.8
  Top Layer w10: v1(1127.92,3449.57) v1@10494.72,3449.57
  Bottom Layer w7: U2.19@10961.65,1704.68 RJ2.2@10961.65,2034.75
  Bottom Layer w10: D35.2@1088.31,440.87 1088.31,988.32 1145.22,1045.22 1295.04,1045.22 ; D2.2@1125.34,3664.02 1125.34,3327.9 837.44,3040 D8.2@837.44,2863.47 837.44,2373.14 951.43,2259.16 D14.2@1111.16,2259.16 1111.16,1733.71 1192.96,1651.91 D20.2@1306.18,1651.91 1306.18,1056.36 ; D29.2@1578.84,1045.22 1317.32,1045.22 ; v1(10491.96,3448.86) 10491.96,2279.86 10586.49,2185.33 10900.3,2185.33 10927.11,2158.52 10927.11,2054.43 10946.79,2034.75 10961.65,2034.75 RJ2.2@10963.33,2034.75 ; 1295.04,1045.22 1308.39,1045.22 ; 1295.04,1045.22 1306.18,1056.36 ; 1306.18,1056.36 1306.18,1047.43 1308.39,1045.22 ; 1306.18,1056.36 1317.32,1045.22 ; 1308.39,1045.22 1317.32,1045.22
CL2: D3.2 D9.2 D15.2 D21.2 D30.2 D36.2 RJ3.2 U2.18 | length 14826.9
  Top Layer w10: v1@1729.53,3409.04 10450.8,3409.04 v1@10453.09,3409.04
  Bottom Layer w7: RJ3.2@10895.63,2032.74 10947.87,1980.5 U2.18@10947.87,1704.68
  Bottom Layer w10: D3.2@1727.53,3664.02 v1(1727.53,3407.63) 1727.53,3287.33 1437.66,2997.46 D9.2@1437.66,2863.47 1437.66,2421.93 1600.44,2259.16 D15.2@1718.18,2259.16 1718.18,1735.34 1801.6,1651.91 D21.2@1909.59,1651.91 1909.59,1056.25 ; D36.2@1847.05,440.87 1847.05,1015.38 1876.89,1045.22 1898.57,1045.22 ; D30.2@2180.6,1045.22 1920.62,1045.22 ; v1@10450.03,3409.04 10450.03,3408.01 10450.03,2263.67 10547.94,2165.76 10835.42,2165.76 10856.93,2144.26 10856.93,2054.91 10876.48,2035.35 RJ3.2@10893.01,2035.35 ; 1898.57,1045.22 1910.11,1045.22 ; 1898.57,1045.22 1909.59,1056.25 ; 1909.59,1056.25 1909.59,1045.74 1910.11,1045.22 ; 1909.59,1056.25 1920.62,1045.22 ; 1910.11,1045.22 1920.62,1045.22
  other v1: 10450.8,3408.01
CL3: D4.2 D10.2 D16.2 D23.2 D31.2 D37.2 RJ4.2 U2.17 | length 15181.8
  Top Layer w10: v1(2339.34,3366.43) v1@10412.94,3366.43
  Bottom Layer w7: RJ4.2@10822.08,2035.54 10822.08,2003.39 10934.09,1891.38 U2.17@10934.09,1704.68
  Bottom Layer w10: D4.2@2339.34,3660.18 v1(2339.34,3366.43) 2339.34,3264.31 2046.27,2971.24 D10.2@2046.27,2863.47 2046.27,2343.49 2130.6,2259.16 D16.2@2312.37,2259.16 2312.37,1728.74 2389.19,1651.91 D23.2@2511.87,1651.91 2511.87,1142.13 2608.78,1045.22 D31.2@2788.24,1045.22 2788.24,672.31 3019.69,440.87 D37.2@4101.36,440.87 ; v1@10407.02,3366.43 10407.02,3366.25 10407.02,2247.23 10553.91,2100.34 10731.18,2100.34 10795.99,2035.54 RJ4.2@10822.08,2035.54
  other v1: 10407.96,3366.25
CL4: D5.2 D11.2 D17.2 D25.2 D32.2 D38.2 RJ5.2 U2.12 | length 14919.6
  Top Layer w10: v1@3116.73,1582.28 3218.84,1684.39 8927.37,1684.39 9068.62,1825.64 10309.41,1825.64 v1(10476.53,1992.75)
  Bottom Layer w7: v1(10476.53,1992.75) 10662.25,1992.75 10672.53,2003.04 RJ5.2@10672.53,2031.32 10715.09,2031.32 10766.54,1979.86 10766.54,1856.87 10865.19,1758.22 U2.12@10865.19,1704.68
  Bottom Layer w10: D5.2@2936.47,3664.15 2936.47,3307.45 2649.36,3020.34 D11.2@2649.36,2863.47 2649.36,2360.03 2750.23,2259.16 D17.2@2920.91,2259.16 2920.91,1706.73 2975.72,1651.91 D25.2@3118.56,1651.91 3118.56,1175.03 3248.37,1045.22 D32.2@3395.27,1045.22 3395.27,795.17 3558.01,632.43 6261.12,632.43 6354.02,539.53 D38.2@6354.02,440.87
  other v1: 3118.28,1587
CL5: D6.2 D12.2 D18.2 D27.2 D33.2 D39.2 RJ6.2 U2.11 | length 14685.4
  Top Layer w10: v1@3719.27,1574.21 3806.28,1661.22 8936.95,1661.22 9071.63,1795.89 10350.57,1795.89 v1(10478.2,1923.52)
  Bottom Layer w7: v1@10478.2,1923.38 10667.27,1923.38 10672.53,1928.65 RJ6.2@10672.53,1959.77 10726.51,1959.77 10748.47,1937.81 10748.47,1840.68 10851.41,1737.73 U2.11@10851.41,1704.68
  Bottom Layer w10: D6.2@3970.6,3664.02 3677.64,3664.02 3257.08,3243.46 D12.2@3257.08,2863.47 3257.08,2374.18 3372.1,2259.16 D18.2@3526.27,2259.16 3526.27,1727.72 3602.08,1651.91 D27.2@3722.2,1651.91 3722.2,1197.12 3874.09,1045.22 D33.2@3997.43,1045.22 3997.43,854.21 4148.88,702.76 7004.33,702.76 7113.58,593.51 D39.2@7113.58,440.87
  other v1: 3724.12,1578.27
CL6: D40.2 D47.2 D54.2 D61.2 D68.2 RJ7.2 U2.10 | length 10475.7
  Top Layer w10: v1@4334.92,1563.38 4409.18,1637.64 8950.18,1637.64 9079.83,1767.29 10390.87,1767.29 v1(10475.87,1852.28)
  Bottom Layer w7: v1@10475.87,1852.62 10664.67,1852.62 10672.53,1860.49 RJ7.2@10672.53,1888.22 10710.97,1888.22 10730.26,1868.92 10730.26,1752.04 10814.58,1667.72 U2.10@10841.57,1667.72
  Bottom Layer w10: D40.2@4576.32,3664.02 4345.53,3664.02 3858.09,3176.58 D47.2@3858.09,2863.47 3858.09,2328.7 3927.64,2259.16 D54.2@4129.96,2259.16 4129.96,1700.79 4184.14,1646.61 D61.2@4332.3,1646.61 4332.3,1163.77 4450.85,1045.22 D68.2@4607.14,1045.22
  other v1: 4333.99,1564.33
CL7: D41.2 D48.2 D55.2 D62.2 D69.2 D74.2 RJ8.2 U2.9 | length 12894.9
  Top Layer w10: v1@4938.68,1558.47 4996.68,1616.46 8967.72,1616.46 9091.44,1740.18 10431,1740.18 v1(10471.54,1780.72)
  Bottom Layer w7: v1@10471.54,1780.42 10662.22,1780.42 10672.53,1790.73 RJ8.2@10672.53,1816.66 10698.07,1816.66 10713.65,1801.07 10713.65,1733.66 10793.37,1653.94 U2.9@10841.57,1653.94
  Bottom Layer w10: D41.2@5185.81,3664.02 4996.11,3664.02 4464.85,3132.77 D48.2@4464.85,2863.47 4464.85,2395.07 4600.76,2259.16 D55.2@4734.14,2259.16 4734.14,1735.7 4819.76,1650.08 D62.2@4937.11,1650.08 4937.11,1154.46 5046.35,1045.22 D69.2@5212.73,1045.22 5212.73,860.84 5299.69,773.88 7789.07,773.88 7910.91,652.04 D74.2@7910.91,440.87
  other v1: 4937.6,1559.46
CL8: D42.2 D49.2 D56.2 D63.2 D70.2 D75.2 RJ9.2 U2.8 | length 12358.7
  Top Layer w10: v1@5539.4,1549.56 5584.14,1594.3 8980.47,1594.3 9095,1708.83 v1(10473.87,1708.83)
  Bottom Layer w7: v1@10473.87,1708.07 10661.74,1708.07 10672.53,1718.86 RJ9.2@10672.53,1743.82 ; RJ9.2@10671.57,1744.78 RJ9.2@10672.53,1743.82 ; RJ9.2@10672.53,1745.11 RJ9.2@10672.53,1743.82 ; U2.8@10841.57,1640.16 10776.19,1640.16 RJ9.2@10672.53,1743.82
  Bottom Layer w10: D42.2@5795.07,3664.02 5491.62,3664.02 5070.47,3242.87 D49.2@5070.47,2863.47 5070.47,2374.04 5185.35,2259.16 D56.2@5342.8,2259.16 5342.8,1765.34 5455.67,1652.47 D63.2@5539.81,1652.47 5539.81,1225.73 5720.32,1045.22 D70.2@5816.55,1045.22 5816.55,898.1 5884.31,830.34 8487.82,830.34 8671.21,646.95 D75.2@8671.21,440.87
  other v1: 5540.52,1552.44
CL9: D43.2 D50.2 D57.2 D64.2 D71.2 RJ10.2 U2.7 | length 9069.8
  Top Layer w10: v1@6140.37,1534.43 6176.91,1570.96 8995.85,1570.96 9102.77,1677.88 10461.39,1677.88 v1(10478.82,1660.46)
  Bottom Layer w7: v1@10475.34,1663.94 v1(10478.82,1660.46) 10508.49,1630.79 10663.07,1630.79 10672.53,1640.25 RJ10.2@10672.53,1673.55 10702.89,1673.55 10750.06,1626.38 U2.7@10841.57,1626.38
  Bottom Layer w10: D71.2@6415.65,1045.22 6224.86,1045.22 6143.38,1126.7 D64.2@6143.38,1652.04 5988.68,1652.04 5945.6,1695.12 D57.2@5945.6,2259.16 5773.99,2259.16 5664.26,2368.9 D50.2@5664.26,2863.47 5664.26,3198.64 5960.83,3495.22 6795.67,3495.22 6885.94,3585.49 D43.2@6885.94,3664.02
  other v1: 6142.72,1539.32
CL10: D44.2 D51.2 D58.2 D65.2 D72.2 RJ11.2 U2.5 | length 8313
  Top Layer w10: v1@6743.09,1533.71 6743.69,1534.31 v1(10461.51,1534.31)
  Bottom Layer w7: v1(10461.51,1534.31) 10550.53,1534.31 10556.32,1528.53 10660.7,1528.53 10671.57,1539.4 RJ11.2@10671.57,1566.03 10704.36,1598.83 U2.5@10841.57,1598.83
  Bottom Layer w10: D72.2@7021.13,1045.22 6838.02,1045.22 6744.15,1139.1 D65.2@6744.15,1651.91 6656.11,1651.91 6556.44,1751.59 D58.2@6556.44,2259.16 6396.86,2259.16 6276.92,2379.1 D51.2@6276.92,2863.47 6276.92,3149.56 6520.28,3392.92 7345.89,3392.92 7494.2,3541.24 D44.2@7494.2,3664.02
  other v1: 6744.52,1532.52
CL11: D45.2 D52.2 D59.2 D66.2 D73.2 RJ12.2 U2.30 | length 11006.1
  Bottom Layer w7: 8261.49,4324.14 10848.53,4324.14 11379.68,3792.99 11379.68,1900.39 11326.56,1847.26 11213.66,1847.26 11202.56,1836.17 11202.56,1812.09 11166.98,1812.09 11143.81,1788.91 11143.81,1650.38 11092.25,1598.83 U2.30@11039.89,1598.83
  Bottom Layer w10: D73.2@8026.22,1045.22 7522.3,1045.22 7353.53,1213.99 D66.2@7353.53,1651.91 7242.18,1651.91 7159.14,1734.95 D59.2@7159.14,2259.16 6993.46,2259.16 6880.5,2372.12 D52.2@6880.5,2863.47 6880.5,3080.14 7060.85,3260.5 7798.94,3260.5 8095.22,3556.78 D45.2@8095.22,3664.02 8095.22,4157.87 8261.49,4324.14
CL12: D46.2 D53.2 D60.2 D67.2 RJ13.2 U2.29 | length 9768.5
  Bottom Layer w7: D67.2@8569.42,2261.92 D67.2@8572.18,2259.16 ; 8698.27,4197.46 8811.96,4311.14 10819.64,4311.14 11366.68,3764.11 11366.68,1953.04 11331.21,1917.57 11212.01,1917.57 11202.56,1908.12 RJ13.2@11202.56,1883.66 ; U2.29@11039.89,1612.6 11087.65,1612.6 11129.29,1654.25 11129.29,1851.09 11161.87,1883.66 RJ13.2@11202.56,1883.66 ; RJ13.2@11202.56,1882.98 RJ13.2@11202.56,1883.66
  Bottom Layer w10: D60.2@7759.08,2259.16 7607.34,2259.16 7487.3,2379.21 D53.2@7487.3,2863.47 7487.3,2990.62 7604.78,3108.1 7778.75,3108.1 8334.68,3664.02 D46.2@8698.27,3664.02 ; D67.2@8572.18,2259.16 8572.18,2462.71 8698.27,2588.8 D46.2@8698.27,3664.02 ; 8698.27,4197.46 D46.2@8698.27,3664.02
CL13: D79.2 D86.2 RJ14.2 U2.28 | length 7498.1
  Top Layer w10: v1(8379.38,3559.54) v1@9511.18,3559.54
  Bottom Layer w7: v1(9511.18,3561.66) 9511.18,3701 9640.61,3830.43 11258.12,3830.43 11353.68,3734.87 11353.68,2021.43 11320.04,1987.78 11210.28,1987.78 11202.56,1980.07 11202.56,1955.24 11162.18,1955.24 11116.29,1909.36 11116.29,1659.64 11083.04,1626.38 U2.28@11039.89,1626.38
  Bottom Layer w10: D86.2@8296.56,1651.91 8296.56,2481.42 8380.15,2565.01 D79.2@8380.15,2863.47 v1@8380.15,3556.91
CL14: D76.2 D80.2 D83.2 D88.2 RJ15.2 U2.27 | length 8195.4
  Top Layer w10: v1(9300.89,2142.44) v1(9506.21,2142.44)
  Bottom Layer w7: D76.2@9584.83,3664.02 9584.83,3733.22 9663.43,3811.82 11224.23,3811.82 11340.68,3695.38 11340.68,2081.96 11322.09,2063.38 11213.52,2063.38 11202.59,2052.45 11202.59,2026.86 11170.62,2026.86 11103.07,1959.32 11103.07,1664.8 11078.44,1640.16 U2.27@11039.89,1640.16
  Bottom Layer w10: v1(9300.89,2142.44) 8945.14,1786.69 8945.14,874.26 9378.53,440.87 D88.2@9590.87,440.87 ; v1(9506.21,2142.44) 9506.21,2183.72 D83.2@9581.65,2259.16 9590.43,2267.94 D80.2@9590.43,2863.47 9584.83,2869.07 D76.2@9584.83,3664.02
CL15: D77.2 D81.2 D84.2 D87.2 D89.2 RJ16.2 U2.26 | length 9498.5
  Top Layer w10: v1@9285.18,2203.24 v1(10190.06,2203.24)
  Bottom Layer w7: D77.2@10187.44,3664.02 10187.44,3748.85 10230.14,3791.55 11200.53,3791.55 11327.59,3664.49 11327.59,2151.32 11310.77,2134.5 11210.03,2134.5 11201.94,2126.41 RJ16.2@11201.94,2098.32 ; U2.26@11039.89,1653.94 11073.83,1653.94 11090.07,1670.18 11090.07,1986.45 RJ16.2@11201.94,2098.32 ; RJ16.2@11201.94,2097.64 RJ16.2@11201.94,2098.32
  Bottom Layer w10: v1(9285.18,2204.8) 8910.65,1830.26 8910.65,864.37 9398.7,376.32 10132.43,376.32 D89.2@10193.66,437.55 10193.66,1044.99 D87.2@10193.89,1045.22 ; D77.2@10187.44,3664.02 10187.44,3513.83 10199.39,3501.88 D81.2@10199.39,2863.47 10199.39,2457.21 10188.64,2446.47 D84.2@10188.64,2259.16 v1@10188.64,2198.32
CL16: D78.2 D82.2 D85.2 D90.2 RJ17.2 U2.25 | length 5136.7
  Top Layer w10: v1(10423.44,1089.97) 10614.28,1089.97 10686.95,1162.64 10686.95,2257.58 v1(10685.17,2259.36)
  Bottom Layer w7: 10798.74,2450.4 10809.62,2461.28 ; 10798.74,2461.28 10809.62,2461.28 ; 10798.74,2475.17 10798.74,2472.16 10809.62,2461.28 ; U2.25@11039.89,1667.72 11069.23,1667.72 11077.07,1675.57 11077.07,2000.11 11159.86,2082.9 11159.86,2128.01 RJ17.2@11201.59,2169.74 ; 10809.62,2461.28 11071.71,2461.28 11202.27,2330.72 RJ17.2@11202.27,2170.42 ; RJ17.2@11201.59,2169.74 RJ17.2@11202.27,2170.42 ; RJ17.2@11201.59,2169.74 RJ17.2@11202.27,2169.74 RJ17.2@11202.27,2170.42
  Bottom Layer w10: v1(10423.44,1089.97) 10406.49,1073.03 10406.49,555.59 10520.99,441.09 D90.2@10798.26,441.09 ; v1(10685.17,2259.36) 10685.37,2259.16 D85.2@10805.09,2259.16 10798.74,2265.51 10798.74,2450.4 10798.74,2461.28 10798.74,2472.16 ; 10798.74,2475.17 D82.2@10798.74,2863.47 10799.68,2864.41 D78.2@10799.68,3664.02
LED_CAP: R127.2 U2.46 | length 11911.2
  Top Layer w7: 8562.11,2184.69 8641.5,2184.69 8951.96,2495.14 9421.18,2495.14 9619,2297.33 10567.14,2297.33 10670.14,2194.33 10670.14,1406.89 10656.94,1393.69 10569.91,1393.69 10552.55,1376.33 v1(10552.55,1338.94)
  Top Layer w10: R127.2@816.54,2033.74 906.42,2033.74 1057.36,2184.69 8562.11,2184.69
  Bottom Layer w7: v1(10552.55,1338.94) 10552.55,1227.21 10609.74,1170.02 10812.05,1170.02 10912.11,1270.08 10912.11,1367.99 10878.97,1401.13 U2.46@10878.97,1506.72
LED_NUM: R126.2 U2.13 | length 3393.9
  Top Layer w7: R126.2@10609,4195.24 10609,4156.63 10625.27,4140.36 11231.01,4140.36 11309.91,4061.45 11309.91,2367.8 10848.54,1906.43 v1(10810.04,1906.43)
  Bottom Layer w7: v1(10810.04,1906.43) 10810.04,1847.17 10878.97,1778.24 U2.13@10878.97,1704.68
LED_SCR: R135.2 U2.14 | length 2823.2
  Top Layer w7: v1(10849.85,1858.12) 10849.85,1885.5 11331.3,2366.96 11331.3,4080.18 11216.25,4195.24 R135.2@11149.66,4195.24
  Bottom Layer w7: v1@10851.88,1860.15 10892.75,1819.28 U2.14@10892.75,1704.68
LLQ1: Q1.2 R1.2 | length 70.8
  Bottom Layer w10: R1.2@10535.74,875.99 Q1.2@10535.74,946.75
LLQ2: Q2.2 R24.2 | length 72.4
  Bottom Layer w10: R24.2@10667.25,875.38 Q2.2@10667.25,947.83
LLQ3: Q3.2 R47.2 | length 71.6
  Bottom Layer w10: R47.2@10800.94,878.72 Q3.2@10800.94,950.32
LLQ4: Q4.2 R70.2 | length 70.4
  Bottom Layer w10: R70.2@10934.85,877.21 Q4.2@10934.85,947.64
LLQ5: Q5.2 R90.2 | length 68.2
  Bottom Layer w10: R90.2@11066.81,878.48 Q5.2@11066.81,946.66
LLQ6: Q6.2 R110.2 | length 70.4
  Bottom Layer w10: R110.2@11203.23,875.91 Q6.2@11203.23,946.29
LR0: Q1.1 U2.38 | length 965.4
  Top Layer w7: v1(10894.92,1210.43) 10915.69,1231.21 v1@11064.79,1231.21
  Bottom Layer w7: Q1.1@10535.74,1021.55 10535.74,1082.57 10609.78,1156.61 10840.04,1156.61 v1@10894.39,1210.96 ; U2.38@10989.21,1506.72 10989.21,1450.05 11021.19,1418.06 11021.19,1273.23 v1@11068.78,1225.64
  other v1: 11063.38,1229.57
LR1: Q2.1 U2.4 | length 706.1
  Top Layer w7: v1@10661.72,1085.46 10704.54,1128.28 10704.54,1550.99 v1(10721.79,1568.24)
  Bottom Layer w7: Q2.1@10665.45,1021.55 v1@10665.45,1096.21 ; v1@10724.53,1568.69 10740.89,1585.05 U2.4@10841.57,1585.05
  other v1: 10665.99,1089.94
LR2: Q3.1 U2.24 | length 1419.6
  Top Layer w7: v1@10872.1,1024.83 10872.1,1116.33 10763.06,1225.37 10763.06,1714.99 10976.69,1928.62 v1(11008.84,1928.62)
  Bottom Layer w7: Q3.1@10800.94,1025.12 v1@10873.07,1025.12 ; v1(11008.84,1928.62) 11038.19,1928.62 11064.07,1902.74 11064.07,1767.62 11030.55,1734.09 U2.24@11030.55,1704.68
  other v1: 10871.81,1028.29
LR3: Q4.1 U2.23 | length 1304.7
  Top Layer w7: v1@10934.49,1043.5 10934.49,1075.31 10776.06,1233.73 10776.06,1707.77 10959.4,1891.11 v1(11010.44,1891.11)
  Bottom Layer w7: Q4.1@10934.85,1022.44 10935.18,1022.78 v1(10935.18,1053.96) ; v1(11010.44,1891.11) 11036.6,1891.11 11051.07,1876.64 11051.07,1785.46 11016.77,1751.16 U2.23@11016.77,1704.68
LR4: Q5.1 U2.22 | length 1305.4
  Top Layer w7: v1(11008.15,1854.93) 10944.54,1854.93 10789.06,1699.46 10789.06,1245.76 11011.5,1023.32 v1@11033.37,1023.32
  Bottom Layer w7: U2.22@11002.99,1704.68 11002.99,1768.5 11038.07,1803.58 11038.07,1844.19 11027.33,1854.93 v1(11008.15,1854.93) ; v1(11023.65,1021.97) 11024.16,1021.46 Q5.1@11066.81,1021.46
LR5: Q6.1 U2.21 | length 1310.2
  Top Layer w7: v1(11006.61,1817.97) 10929.97,1817.97 10802.06,1690.06 10802.06,1255.62 10974.47,1083.22 11059.15,1083.22 v1@11119.21,1023.16
  Bottom Layer w7: U2.21@10989.21,1704.68 10989.21,1800.57 v1(11006.61,1817.97) ; v1(11120.14,1024.09) 11123.14,1021.09 Q6.1@11203.23,1021.09
NetC3_2: C3.2 D22.2 D24.1 U1.2 | length 742
  Bottom Layer w20: 9858.53,1510.2 9858.53,1508.02 ; U1.2@9904.01,1492.78 9873.77,1492.78 ; D24.1@10039.49,1358.69 10039.38,1358.58 C3.2@9901.41,1358.58 9874.35,1358.58 9858.53,1374.4 9858.53,1477.53 ; D22.2@10049.12,1677.06 10049.12,1601.96 10034.3,1587.14 9894.74,1587.14 9858.53,1550.93 9858.53,1508.02 ; 9858.53,1477.53 9858.53,1492.04 ; 9858.53,1477.53 9873.77,1492.78 ; 9858.53,1492.04 9858.53,1508.02 ; 9858.53,1492.04 9859.26,1492.78 9873.77,1492.78 ; 9858.53,1508.02 9873.77,1492.78
NetC10_1: C10.1 C11.1 C12.1 D26.1 L4.2 R131.1 | length 690.9
  Bottom Layer w30: L4.2@9374.78,1337.41 9374.78,1249.72 R131.1@9373.45,1248.39 9426.42,1248.39 9444.56,1230.25 C10.1@9444.56,1170.04 9444.56,1169.57 9444.56,995.5 C12.1@9448.23,991.82 ; C12.1@9448.44,991.61 C12.1@9448.23,991.82 ; D26.1@9609.18,873.84 9608.33,874.69 C11.1@9445.37,874.69 9445.37,988.96 C12.1@9448.23,991.82
NetC10_2: C10.2 R131.2 R133.2 U3.5 | length 590.4
  Bottom Layer w20: U3.5@9133.76,1537.45 9165.75,1537.45 9181.35,1521.85 9181.35,1285.89 9218.85,1248.39 R131.2@9312.82,1248.39 9313.87,1247.34 R133.2@9313.87,1171.89 9315.72,1170.04 C10.2@9389.56,1170.04
NetD1_1: D1.1 S1.2 | length 130.9
  Top Layer w10: S1.2@339.9,3793.8 339.9,3744.95 v1(341.44,3743.41)
  Bottom Layer w10: D1.1@340.22,3664.02 340.22,3742.2 v1(341.44,3743.41)
NetD2_1: D2.1 S2.2 | length 128
  Top Layer w10: v1(1233.4,3736.79) 1233.77,3737.16 S2.2@1233.77,3793.8
  Bottom Layer w10: D2.1@1233.4,3665.96 v1(1233.4,3736.79)
NetD3_1: D3.1 S3.2 | length 143.2
  Top Layer w10: S3.2@1838.31,3801.45 S3.2@1838.31,3793.8 1838.31,3745.07 v1(1839.29,3744.08)
  Bottom Layer w10: D3.1@1839.29,3658.67 v1(1839.29,3744.08)
NetD4_1: D4.1 S4.2 | length 134
  Top Layer w10: v1(2440.39,3741.77) 2440.39,3791.35 S4.2@2442.84,3793.8
  Bottom Layer w10: D4.1@2440.39,3660.85 v1(2440.39,3741.77)
NetD5_1: D5.1 S5.2 | length 131.4
  Top Layer w10: S5.2@3047.38,3793.8 3047.38,3737.28 v1(3049.01,3735.65)
  Bottom Layer w10: D5.1@3046.47,3664.15 3046.47,3733.11 v1(3049.01,3735.65)
NetD6_1: D6.1 S6.2 | length 156.5
  Top Layer w10: v1(4080.31,3733.16) S6.2@4080.31,3798.94
  Bottom Layer w10: v1(4080.31,3733.16) 4080.31,3740.88 4080.6,3741.17 D6.1@4080.6,3664.02 D6.1@4080.6,3658.56
NetD7_1: D7.1 S7.2 | length 132.8
  Top Layer w10: v1(346.44,2929.95) S7.2@346.44,2996.28
  Bottom Layer w10: D7.1@346.44,2863.47 v1(346.44,2929.95)
NetD8_1: D8.1 S8.2 | length 138
  Top Layer w10: v1(945.43,2932.48) S8.2@945.45,2994.96
  Bottom Layer w10: D8.1@945.43,2856.93 v1(945.43,2932.48)
NetD9_1: D9.1 S9.2 | length 140.7
  Top Layer w10: v1(1547.66,2938.16) S9.2@1547.66,2998.93
  Bottom Layer w10: D9.1@1547.66,2858.26 D9.1@1547.66,2863.47 v1(1547.66,2938.16)
NetD10_1: D10.1 S10.2 | length 137.2
  Top Layer w10: v1(2157.01,2940.12) S10.2@2157.01,3000.34
  Bottom Layer w10: D10.1@2156.27,2863.47 2157.01,2864.21 v1(2157.01,2940.12)
NetD11_1: D11.1 S11.2 | length 139.7
  Top Layer w10: v1(2756.72,2935.9) S11.2@2756.72,3002.07
  Bottom Layer w10: v1(2756.72,2935.9) 2756.72,2866.11 D11.1@2759.36,2863.47
NetD12_1: D12.1 S12.2 | length 139.8
  Top Layer w10: v1(3367.08,2932.82) S12.2@3367.08,2997.88
  Bottom Layer w10: D12.1@3367.08,2858.06 D12.1@3367.08,2863.47 v1(3367.08,2932.82)
NetD13_1: D13.1 S13.2 | length 134.8
  Top Layer w10: v1(520.39,2334.02) S13.2@520.39,2393.7
  Bottom Layer w10: v1(520.39,2334.02) 520.39,2259.88 D13.1@521.11,2259.16
NetD14_1: D14.1 S14.2 | length 132.1
  Top Layer w10: v1(1221.91,2329.7) S14.2@1221.91,2390.91
  Bottom Layer w10: D14.1@1221.16,2259.16 1221.91,2259.91 v1(1221.91,2329.7)
NetD15_1: D15.1 S15.2 | length 130
  Top Layer w10: v1(1828.18,2327.46) S15.2@1828.18,2389.19
  Bottom Layer w10: D15.1@1828.18,2259.16 v1(1828.18,2327.46)
NetD16_1: D16.1 S16.2 | length 129.5
  Top Layer w10: v1(2422.37,2327.89) S16.2@2422.37,2388.7
  Bottom Layer w10: D16.1@2422.37,2259.16 v1(2422.37,2327.89)
NetD17_1: D17.1 S17.2 | length 130.1
  Top Layer w10: S17.2@3029.61,2388.74 3030.22,2388.14 v1(3030.22,2329.1)
  Bottom Layer w10: v1(3030.22,2329.1) 3030.22,2259.85 D17.1@3030.91,2259.16
NetD18_1: D18.1 S18.2 | length 131.7
  Top Layer w10: v1(3636.27,2336.87) S18.2@3636.27,2390.82
  Bottom Layer w10: D18.1@3636.27,2259.16 v1(3636.27,2336.87)
NetD19_1: D19.1 S19.2 | length 141.8
  Top Layer w10: v1(637.64,1731.27) S19.2@637.64,1795.04
  Bottom Layer w10: D19.1@637.64,1653.26 v1(637.64,1731.27)
NetD20_1: D20.1 S20.2 | length 140.8
  Top Layer w10: v1(1412.23,1729.57) S20.2@1412.23,1787.5
  Bottom Layer w10: D20.1@1412.23,1646.71 v1(1412.23,1729.57)
NetD21_1: D21.1 S21.2 | length 137.4
  Top Layer w10: v1(2022.85,1732.52) S21.2@2022.85,1786.29
  Bottom Layer w10: D21.1@2022.85,1648.91 v1(2022.85,1732.52)
NetD22_1: D22.1 L1.2 U1.5 | length 294.4
  Bottom Layer w20: U1.5@9809.52,1530.18 9782.9,1530.18 9761.6,1551.48 L1.2@9761.6,1676.23 9762.43,1677.06 D22.1@9874.12,1677.06
NetD23_1: D23.1 S22.2 | length 139.5
  Top Layer w10: v1(2628.47,1732.11) S22.2@2628.47,1791.36
  Bottom Layer w10: D23.1@2628.47,1651.83 v1(2628.47,1732.11)
NetD25_1: D25.1 S23.2 | length 140.8
  Top Layer w10: v1(3233.43,1727.37) S23.2@3233.43,1787.94
  Bottom Layer w10: D25.1@3233.43,1647.15 v1(3233.43,1727.37)
NetD27_1: D27.1 S24.2 | length 136.4
  Top Layer w10: v1(3831.13,1729.93) S24.2@3831.13,1787.88
  Bottom Layer w10: v1(3831.13,1729.93) 3831.13,1652.98 D27.1@3832.2,1651.91
NetD28_1: D28.1 S25.2 | length 132.2
  Top Layer w10: v1(720.9,1121.62) S25.2@720.9,1177.44
  Bottom Layer w10: D28.1@720.9,1045.22 v1(720.9,1121.62)
NetD29_1: D29.1 S26.2 | length 133.9
  Top Layer w10: S26.2@1688.15,1178.83 1688.3,1178.68 v1(1688.3,1121.71)
  Bottom Layer w10: v1(1688.3,1121.71) 1688.3,1045.75 D29.1@1688.84,1045.22
NetD30_1: D30.1 S27.2 | length 135.5
  Top Layer w10: v1(2292.9,1113.5) S27.2@2292.9,1180.71
  Bottom Layer w10: D30.1@2290.6,1045.22 v1@2290.6,1113.5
